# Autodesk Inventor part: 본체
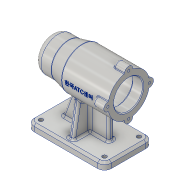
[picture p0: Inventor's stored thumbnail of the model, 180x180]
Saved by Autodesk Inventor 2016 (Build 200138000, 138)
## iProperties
Created: 2019-07
Part Number: 본체
Material: 알루미늄 6061
Document SubType Name: Modeling
Designer: 605-17
Density: 2.7 g/cm^3
Appearance: 알루미늄 - 평지
Mass: 644.389 g
Surface Area: 654.079 cm^2
Volume: 238.663 cm^3
Author: 605-17
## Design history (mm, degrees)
sketch "스케치1"
  geometry: L1 (-56, 0)-(56, 0); L2 (-56, 0)-(-56, 25); L3 (-56, 25)-(-31, 25); L4 (-31, 25)-(-11, 30); L5 (-11, 30)-(56, 30); L6 (56, 30)-(56, 21); L7 (56, 21)-(41, 21); L8 (41, 21)-(41, 24); L9 (41, 24)-(-13, 24); L10 (-13, 24)-(-13, 21); L11 (-13, 21)-(-25, 21); L12 (-25, 21)-(-25, 17.5); L13 (-25, 17.5)-(-43, 17.5); L14 (-43, 17.5)-(-43, 16); L15 (-43, 16)-(-47, 16); L16 (-47, 16)-(-47, 10.5); L17 (-47, 10.5)-(-50, 10.5); L18 (-50, 10.5)-(-50, 0); L19 (-50, 0)-(-56, 0); 1 further point
  constraints: 38 end point, 13 perpendicular, 2 vertical, 1 collinear, 1 horizontal, 1 horizontal alignment, 1 parallel, 1 point on line, 1 vertical alignment
  dimensions: "d0" = 112 distance of L1.start L1.end; "d1" = 56 distance of L1.start point (0, 0); "d3" = 48 diameter of L9 L1; "d4" = 50 diameter of L3 L1; "d5" = 25 distance from line of L3.end L2; "d6" = 45 horizontal distance of L4.end L2.end; "d7" = 42 diameter of L7 L1; "d8" = 42 diameter of L11 L1; "d9" = 35 diameter of L13 L1; "d10" = 32 diameter of L15 L1; "d11" = 21 diameter of L17 L1; "d12" = 15 distance of L6.end L7.end; "d13" = 54 distance of L8.end L9.end; "d14" = 12 distance between parallel lines of L10 L12; "d15" = 18 distance between parallel lines of L14 L12; "d16" = 4 distance between parallel lines of L14 L16; "d17" = 3 distance between parallel lines of L18 L16; "d83" = 60 diameter of L5 L1
revolve "회전1" sketch "스케치1" stored, may be unused: angle "d18" = 90 deg
fillet "모깎기1" dims "d19" = 0.3
fillet "모깎기2" dims "d20" = 3
chamfer "모따기1" distance "d21" = 1; stored, may be unused: second distance "d22" = 2, angle "d23" = 45 deg
sketch "스케치2"
  geometry: L1 (-6, 30)-(-6, 29.394); L2 (6, 30)-(6, 29.394); A1 r 30 centre (0, 0) between (0, 30) and (6, 29.394) reference; A2 r 6 centre (0, 30) between (6, 30) and (-6, 30); A3 r 30 centre (0, 0) between (6, 29.394) and (-6, 29.394); 1 further point
  constraints: 7 point on circle, 4 end point, 2 centre point, 2 tangent, 2 vertical, 1 coincident, 1 vertical alignment
  dimensions: "d24" = 6 radius of A2
extrude "돌출1" join sketch "스케치2" distance "d25" = 16; taper "d26" = 0 deg
fillet "모깎기3" dims "d27" = 3
fillet "모깎기4" dims "d28" = 1
sketch "스케치3"
  geometry: A1 r 6 centre (0, 0) between (5.998, 0.171) and (-5.998, 0.171) reference; A2 r 6 centre (30, -30) between (30.171, -35.998) and (30.171, -24.002) reference; A3 r 6 centre (-30, -30) between (-30.171, -24.002) and (-30.171, -35.998) reference; A4 r 6 centre (0, -60) between (-5.998, -60.171) and (5.998, -60.171) reference; 1 further point
hole "구멍1" sketch "스케치3" at (0, 0), (-30, -30), (0, -60), (30, -30) diameter "d32" = 3.242; stored, may be unused: countersink angle "d36" = 90 deg, drill point angle "d38" = 120 deg; dims "d33" = 8, "d34" = 4, "d35" = 2, "d37" = 11
sketch "스케치4"
  geometry: L1 (-35, -100)-(35, -100); L2 (35, -100)-(35, -110); L3 (35, -110)-(-35, -110); L4 (-35, -110)-(-35, -100); 2 further points
  constraints: 8 end point, 2 parallel, 1 horizontal, 1 midpoint, 1 perpendicular, 1 vertical alignment
  dimensions: "d39" = 70 distance of L2.end L3.end; "d40" = 10 distance between parallel lines of L1 L3; "d41" = 80 distance from line of point (0, -30) L3
extrude "돌출2" join sketch "스케치4" distance "d42" = 112; taper "d43" = 0 deg
sketch "스케치5"
  geometry: L1 (-70, 35)-(-70, -35) reference; L2 (-15.435, 18.379)-(-70, 28); L3 (-80, 35)-(-70, 35) reference; L4 (-15.435, -18.379)-(-70, -28); L5 (-70, 28)-(-70, -28); A1 r 24 centre (0, 0) between (-15.435, 18.379) and (-15.435, -18.379) reference; A2 r 24 centre (0, 0) between (-15.435, 18.379) and (-15.435, -18.379); 1 further point
  constraints: 6 end point, 4 point on circle, 2 point on line, 1 centre point, 1 coincident, 1 vertical
  dimensions: "d44" = 7 distance from line of L2.end L3; "d45" = 100 deg angle of L1 L2; "d46" = 100 deg angle of L1 L4; "d47" = 7 distance of L4.end L1.end
extrude "돌출3" join sketch "스케치5" stored distance "d48" = 8; taper "d49" = 0 deg
sketch "스케치6"
  geometry: L1 (-11, -30)-(39, -30) reference; L2 (56, -70)-(-56, -70) reference; L3 (31, -30)-(31, -70); L4 (56, -70)-(56, -80) reference; 1 further point
  constraints: 2 end point, 2 point on line, 1 perpendicular
  dimensions: "d50" = 25 distance between parallel lines of L4 L3
feature "리브1" sketch "스케치6" dims "d51" = 1, "d52" = 8, "d53" = 0, "d54" = 0, "d55" = 1, "d56" = 1
sketch "스케치7"
  geometry: L1 (-31, -25)-(-11, -30) reference; L2 (56, -70)-(-56, -70) reference; L3 (-20.57, -27.607)-(-36, -70); L4 (-56, -70)-(-56, -80) reference; 1 further point
  constraints: 2 end point, 2 point on line
  dimensions: "d57" = 110 deg angle of L2 L3; "d58" = 20 distance from line of L4 L3.end
feature "리브2" sketch "스케치7" dims "d59" = 1, "d60" = 8, "d61" = 0, "d62" = 0, "d63" = 1, "d64" = 1
fillet "모깎기5" dims "d65" = 10
chamfer "모따기2" distance "d66" = 3; stored, may be unused: second distance "d67" = 2, angle "d68" = 45 deg
sketch "스케치8"
  geometry: A1 r 10 centre (0, 57) between (0, 67) and (-10, 57) reference; A2 r 10 centre (92, 57) between (102, 57) and (92, 67) reference; A3 r 10 centre (92, 7) between (92, -3) and (102, 7) reference; A4 r 10 centre (0, 7) between (-10, 7) and (0, -3) reference; 1 further point
hole "구멍2" sketch "스케치8" at (0, 57), (0, 7), (92, 7), (92, 57) diameter "d69" = 6; stored, may be unused: countersink angle "d73" = 90 deg, drill point angle "d75" = 120 deg; dims "d70" = 8, "d71" = 4, "d72" = 2, "d74" = 11
fillet "모깎기6" dims "d76" = 10
fillet "모깎기7" dims "d77" = 3
fillet "모깎기8" dims "d78" = 3
node "작업 평면1"
sketch "스케치9"
  geometry: L1 (33.5, 6.771)-(33.5, 29.226) reference; 2 further points
  constraints: 1 horizontal alignment, 1 other
  dimensions: "d80" = 42 distance from line of L1 point (-8.5, 0)
feature "엠보싱1" sketch "스케치9" dims "d18" = 90 deg, "d81" = 0.5, "d82" = 0
fillet "모깎기10" dims "d84" = 3
fillet "모깎기11" dims "d85" = 3
node "솔리드1"
pattern_circular "원형 패턴1" dims "d30" = 360 deg
